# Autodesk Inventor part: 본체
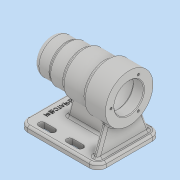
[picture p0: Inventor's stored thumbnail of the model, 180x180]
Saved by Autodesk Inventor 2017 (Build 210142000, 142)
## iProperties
Part Number: 본체
Material: 일반
Document SubType Name: Modeling
Designer: MRC
Density: 1 g/cm^3
Appearance: 기본값
Mass: 255.944 g
Surface Area: 699.291 cm^2
Volume: 255.944 cm^3
Author: MRC
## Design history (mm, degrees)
sketch "스케치1"
  geometry: C1 r 34 at (0, 0); 1 further point
  constraints: 1 centre point, 1 coincident
  dimensions: "d0" = 68 diameter of C1
extrude "돌출1" new body sketch "스케치1" distance "d1" = 32; taper "d2" = 0 deg
sketch "스케치2"
  geometry: C1 r 30 at (0, 0); 1 further point
  constraints: 1 centre point, 1 coincident
  dimensions: "d3" = 60 diameter of C1
extrude "돌출2" join sketch "스케치2" distance "d4" = 34; taper "d5" = 0 deg
sketch "스케치3"
  geometry: C1 r 27 at (0, 0); 1 further point
  constraints: 1 centre point, 1 coincident
  dimensions: "d6" = 54 diameter of C1
extrude "돌출3" join sketch "스케치3" distance "d7" = 22; taper "d8" = 0 deg
sketch "스케치4"
  geometry: C1 r 25 at (0, 0); 1 further point
  constraints: 1 centre point, 1 coincident
  dimensions: "d9" = 50 diameter of C1
extrude "돌출4" join sketch "스케치4" distance "d10" = 24; taper "d11" = 0 deg
fillet "모깎기1" dims "d12" = 8
sketch "스케치5"
  geometry: L1 (-45, -62)-(45, -62); L2 (45, -62)-(45, -70); L3 (45, -70)-(-45, -70); L4 (-45, -70)-(-45, -62); L5 (-45, -62)-(45, -70); L6 (45, -62)-(-45, -70); 3 further points
  constraints: 12 end point, 3 midpoint, 2 parallel, 1 horizontal, 1 perpendicular, 1 vertical alignment
  dimensions: "d13" = 70 distance from line of L3 point (0, 0); "d14" = 8 distance between parallel lines of L3 L1; "d15" = 90 distance between parallel lines of L2 L4
extrude "돌출5" join sketch "스케치5" distance "d16" = 112; taper "d17" = 0 deg
fillet "모깎기2" dims "d18" = 12
node "작업 평면1"
sketch "스케치6"
  geometry: L1 (-45, -62)-(-45, -70) reference; L2 (-37, -62)-(-14.434, 0); L3 (-14.434, 0)-(0, 0); L4 (-45, -62)-(-33, -62) reference; L5 (0, 0)-(0, -62); L6 (0, -62)-(-37, -62); L7 (14.434, 0)-(0, 0); L8 (0, -62)-(37, -62); L9 (14.434, 0)-(37, -62); 1 further point
  constraints: 14 end point, 2 horizontal alignment, 2 perpendicular, 2 symmetric about line, 1 parallel
  dimensions: "d21" = 8 distance from line of L1 L2.start; "d22" = 110 deg angle of L4 L2
extrude "돌출6" join sketch "스케치6" distance "d23" = 8; taper "d24" = 0 deg
sketch "스케치7"
  geometry: L1 (-62, -8)-(-24.658, -8) reference; L2 (-62, -8)-(-62, -85); L3 (-62, -12)-(-62, -100) reference; L4 (-62, -85)-(-3.891, -69.43); L5 (-3.891, -69.43)-(-3.891, -16); L6 (-3.891, -16)-(-62, -16); 1 further point
  constraints: 8 end point, 2 point on line, 1 perpendicular, 1 vertical
  dimensions: "d25" = 77 distance of L1.start L2.end; "d26" = 105 deg angle of L2 L4
extrude "돌출7" join sketch "스케치7" stored distance "d27" = 8; taper "d28" = 0 deg
fillet "모깎기3" dims "d29" = 3
sketch "스케치8"
  geometry: L1 (0, 0)-(0, -112); L2 (17, -112)-(-17, -112) reference; L3 (-34, 0)-(34, 0) reference; L4 (0, 0)-(21, 0); L5 (21, 0)-(21, -15); L6 (21, -15)-(0, -15); L7 (0, -15)-(24, -15); L8 (24, -18)-(24, -66); L9 (21, -69)-(0, -69); L10 (0, -69)-(0, -15); L11 (0, -69)-(21, -69); L12 (21, -69)-(21, -80.7); L13 (20.7, -81)-(0, -81); L14 (0, -81)-(0, -69); L15 (0, -81)-(17.5, -81); L16 (17.5, -81)-(17.5, -98.7); L17 (17.2, -99)-(0, -99); L18 (0, -99)-(0, -81); L19 (0, -99)-(16, -99); L20 (16, -99)-(16, -102.7); L21 (15.7, -103)-(0, -103); L22 (0, -103)-(0, -99); L23 (0, -103)-(10.5, -103); L24 (10.5, -103)-(10.5, -103); L25 (7.5, -106)-(0, -106); L26 (0, -106)-(0, -103); A1 r 3 centre (7.5, -103) between (7.5, -106) and (10.5, -103); A2 r 0.3 centre (15.7, -102.7) between (15.7, -103) and (16, -102.7); A3 r 0.3 centre (17.2, -98.7) between (17.2, -99) and (17.5, -98.7); A4 r 0.3 centre (20.7, -80.7) between (20.7, -81) and (21, -80.7); A5 r 3 centre (21, -66) between (21, -69) and (24, -66); A6 r 3 centre (21, -18) between (24, -18) and (21, -15)
  constraints: 48 end point, 12 point on circle, 12 tangent, 10 parallel, 7 perpendicular, 6 centre point, 5 horizontal, 4 equal radius, 4 point on line, 1 midpoint
  dimensions: "d31" = 21 distance of L1.start L4.end; "d32" = 15 distance of L4.end L5.end; "d33" = 48 diameter of L8 L1; "d34" = 54 distance between parallel lines of L9 L6; "d35" = 42 diameter of L12 L1; "d36" = 12 distance between parallel lines of L9 L13; "d37" = 18 distance between parallel lines of L13 L17; "d38" = 35 diameter of L16 L1; "d39" = 32 diameter of L20 L1; "d40" = 4 distance between parallel lines of L17 L21; "d41" = 21 diameter of L24 L1; "d42" = 3 distance between parallel lines of L21 L25; "d43" = 3 radius of A1; "d44" = 0.3 radius of A2
revolve "회전1" sketch "스케치8" stored, may be unused: angle "d45" = 90 deg
chamfer "모따기1" distance "d46" = 1; stored, may be unused: second distance "d47" = 2, angle "d48" = 45 deg
fillet "모깎기4" dims "d49" = 3
fillet "모깎기5" dims "d50" = 3
sketch "스케치9"
  geometry: L1 (0, -17)-(0, -32); L2 (-4.5, -17)-(-4.5, -32); L3 (4.5, -32)-(4.5, -17); L4 (66, 3)-(0, 3) reference; L5 (33, -109)-(33, 3); L6 (0, -57)-(0, -72); L7 (3, -77)-(3, -43) reference; L8 (4.5, -57)-(4.5, -72); L9 (-4.5, -72)-(-4.5, -57); A1 r 4.5 centre (0, -17) between (4.5, -17) and (-4.5, -17); A2 r 4.5 centre (0, -32) between (-4.5, -32) and (4.5, -32); A3 r 4.5 centre (0, -57) between (4.5, -57) and (-4.5, -57); A4 r 4.5 centre (0, -72) between (-4.5, -72) and (4.5, -72); 2 further points
  constraints: 18 end point, 8 point on circle, 8 tangent, 4 centre point, 3 midpoint, 3 parallel, 1 vertical, 1 vertical alignment
  dimensions: "d51" = 9 diameter of A2; "d52" = 20 distance from line of L4 L1.start; "d53" = 33 distance between parallel lines of L1 L5; "d54" = 15 distance of L1.end L1.start; "d55" = 25 distance of L1.end L6.start; "d56" = 15 distance of L6.end L6.start; "d57" = 4.5 radius of A4
extrude "돌출8" cut sketch "스케치9" stored distance "d58" = 8; taper "d59" = 0 deg
sketch "스케치10"
  geometry: L1 (16, 3)-(50, 3) reference; 2 further points
  constraints: 1 other
  dimensions: "d60" = 12 distance from line of L1 point (33, -9)
feature "엠보싱1" sketch "스케치10" dims "d61" = 0.5, "d62" = 0
sketch "스케치11" dims "d63" = 52
  geometry: 5 further points
  constraints: 1 coincident, 1 horizontal alignment, 6 other
  dimensions: "d66" = 360 deg dimension on point (0, 0) point (-26, 0) (derived)
hole "구멍1" sketch "스케치11" at (-26, 0), (13, -22.517), (13, 22.517) diameter "d68" = 3.242; stored, may be unused: countersink angle "d72" = 90 deg, drill point angle "d74" = 118 deg; dims "d69" = 8, "d70" = 4, "d71" = 2, "d73" = 11
fillet "모깎기6" dims "d75" = 3
fillet "모깎기7" dims "d76" = 3
fillet "모깎기8" dims "d77" = 3
node "솔리드1"
mirror "미러1"
other parameters: "d19" = -8
